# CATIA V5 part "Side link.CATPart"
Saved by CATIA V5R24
Part number: Side link
Bounding box of the stored display mesh (mm): x -8.5 to 8.5, y -25.4 to -19.6, z 0 to 2.8
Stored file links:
  C:\Users\Jules\Documents\ECL\Watch\Side link.CATPart
  C:\Users\Jules\Documents\ECL\Watch\Midle link.CATPart
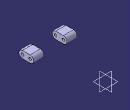
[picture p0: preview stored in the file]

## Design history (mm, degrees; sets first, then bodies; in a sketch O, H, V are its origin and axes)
Body1 (main body)
  Sketch1 on yz-plane, origin (0, 0, 0), H (0, 1, 0), V (0, 0, 1)
    line L1 (-24, 2.8) -> (-21, 2.8)
    arc A1 centre (-21, 1.4) radius 1.4 from (-21, 2.8) to (-21, 0) cw
    point P3 (-21, 1.4)
    point P4 (-21, 0)
    line L2 (-21, 0) -> (-24, 0)
    arc A2 centre (-24, 1.4) radius 1.4 from (-24, 0) to (-24, 2.8) cw
    circle A3 centre (-21, 1.4) radius 0.55
    circle A4 centre (-24, 1.4) radius 0.55
    radius A1 = 1.4
    length L2 = 3
    distance P3 V = 21
    radius A3 = 0.55
    radius A4 = 0.55
    horizontal: L1 H
    coincidence: P4 H
    tangency: A1 L1, L2 A1, A2 L1, A2 L2
  Pad1: profile Sketch1, direction (1, 0, 0), length 8.5, mirrored extent
  Sketch2 on xy-plane, origin (0, 0, 0), H (1, 0, 0), V (0, 1, 0)
    line L1 (-4.5, -19.2468) -> (4.5, -19.2468)
    line L2 (4.5, -19.2468) -> (4.5, -25.8459)
    line L3 (4.5, -25.8459) -> (-4.5, -25.8459)
    line L4 (-4.5, -25.8459) -> (-4.5, -19.2468)
    length L3 = 9
    horizontal: L1 H, L3 H
    vertical: L2 V, L4 V
    symmetry: L4 L2 V
  Pocket1: profile Sketch2, direction (0, 0, -1), length 8.5, mirrored extent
